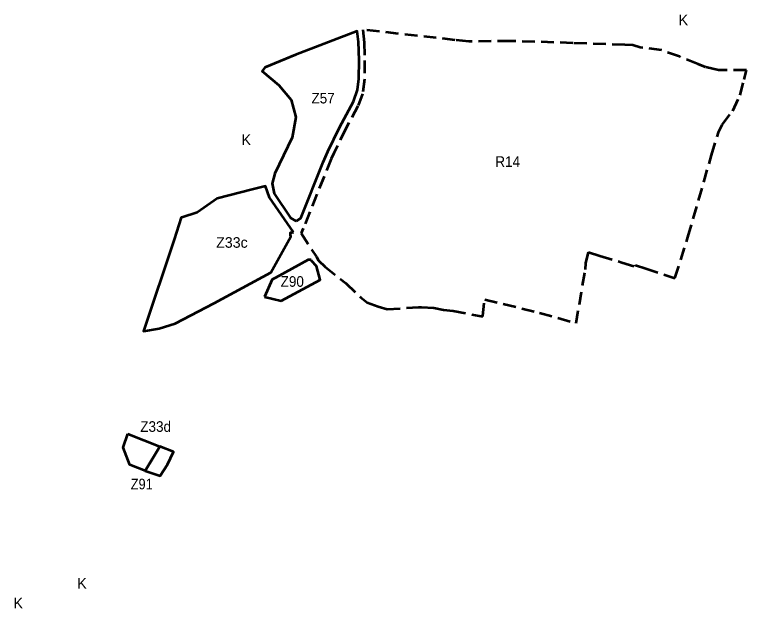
# Model space of a CAD drawing. Extents: x -650246 to -642674, y -1074280 to -1066767.
# Drawn here: x -648810 to -647155, y -1074280 to -1072937 of the extents above; entities that cross this region are included whole.
import ezdxf

# ---------------------------------------------------------------- set-up
doc = ezdxf.new("R2010")
doc.units = 0
doc.header["$LTSCALE"] = 9.6
doc.linetypes.add('MEDIUM_DASHED', pattern=[4.5, 3, -1.5])
for name, color, linetype, lineweight in [('44', 7, 'Continuous', 53), ('45', 7, 'Continuous', 53), ('46', 7, 'Continuous', 13), ('48', 7, 'Continuous', 13), ('61', 7, 'MEDIUM_DASHED', 53), ('62', 7, 'Continuous', 35)]:
    doc.layers.add(name, color=color, linetype=linetype, lineweight=lineweight)

msp = doc.modelspace()

# ---------------------------------------------------------------- linework, layer by layer
at = {"layer": '44'}
msp.add_line((-648245.341, -1073575.152), (-648207, -1073584), dxfattribs=at)
for points in [[(-648139.56, -1073491.4), (-648146.4, -1073491.55), (-648220.42, -1073532.43), (-648227.63, -1073535.89), (-648245.341, -1073575.152)], [(-648207, -1073584), (-648119, -1073537), (-648127.31, -1073505.75), (-648138.41, -1073493.62), (-648139.56, -1073491.4)]]:
    msp.add_lwpolyline(points, dxfattribs=at)
msp.add_lwpolyline([(-648515.333, -1073968.584), (-648480.86, -1073980.25), (-648464.44, -1073954.69), (-648451.05, -1073925.87), (-648481.749, -1073913.76), (-648498, -1073940)], close=True, dxfattribs=at)
at = {"layer": '45'}
for points in [[(-648030.86, -1073039.71), (-648032.09, -1072998.65), (-648035.592, -1072974.222), (-648175.061, -1073027.551), (-648244.214, -1073056.657), (-648250.491, -1073064.698), (-648212.22, -1073096.39), (-648184.37, -1073129.89)], [(-648030.86, -1073039.71), (-648032.09, -1072998.65), (-648035.592, -1072974.222), (-648175.061, -1073027.551), (-648244.214, -1073056.657), (-648250.491, -1073064.698), (-648212.22, -1073096.39), (-648184.37, -1073129.89)], [(-648101.67, -1073246.63), (-648075.34, -1073191.93), (-648043.29, -1073132.97), (-648034.43, -1073107.07), (-648031.8, -1073082.07), (-648030.86, -1073039.71)], [(-648101.67, -1073246.63), (-648075.34, -1073191.93), (-648043.29, -1073132.97), (-648034.43, -1073107.07), (-648031.8, -1073082.07), (-648030.86, -1073039.71)], [(-648184.37, -1073129.89), (-648174.03, -1073168.94), (-648182.12, -1073214.56), (-648221.39, -1073296.24), (-648227.75, -1073318.75), (-648223.03, -1073341.59), (-648186.47, -1073396.47), (-648173.38, -1073404.03)], [(-648184.37, -1073129.89), (-648174.03, -1073168.94), (-648182.12, -1073214.56), (-648221.39, -1073296.24), (-648227.75, -1073318.75), (-648223.03, -1073341.59), (-648186.47, -1073396.47), (-648173.38, -1073404.03)], [(-648173.38, -1073404.03), (-648162.55, -1073397.4), (-648112.36, -1073270.87), (-648101.67, -1073246.63)], [(-648173.38, -1073404.03), (-648162.55, -1073397.4), (-648112.36, -1073270.87), (-648101.67, -1073246.63)], [(-648179.07, -1073428.81), (-648233.36, -1073350.68), (-648243.08, -1073325.04), (-648272.642, -1073332.558)], [(-648179.07, -1073428.81), (-648233.36, -1073350.68), (-648243.08, -1073325.04), (-648272.642, -1073332.558)], [(-648272.642, -1073332.558), (-648352.312, -1073353), (-648397.062, -1073384.375)], [(-648272.642, -1073332.558), (-648352.312, -1073353), (-648397.062, -1073384.375)], [(-648397.062, -1073384.375), (-648432.187, -1073395.625), (-648433.206, -1073395.51), (-648449.599, -1073445.278)], [(-648397.062, -1073384.375), (-648432.187, -1073395.625), (-648433.206, -1073395.51), (-648449.599, -1073445.278)], [(-648447.06, -1073635.39), (-648358.69, -1073589.35), (-648230.81, -1073520.18), (-648185.34, -1073438.91), (-648185.82, -1073435.12), (-648186.46, -1073430.01), (-648183.46, -1073429.52), (-648179.07, -1073428.81)], [(-648447.06, -1073635.39), (-648358.69, -1073589.35), (-648230.81, -1073520.18), (-648185.34, -1073438.91), (-648185.82, -1073435.12), (-648186.46, -1073430.01), (-648183.46, -1073429.52), (-648179.07, -1073428.81)], [(-648449.599, -1073445.278), (-648518.867, -1073652.836), (-648483.58, -1073646.7), (-648447.06, -1073635.39), (-648447.06, -1073635.39)], [(-648449.599, -1073445.278), (-648518.867, -1073652.836), (-648483.58, -1073646.7), (-648447.06, -1073635.39), (-648447.06, -1073635.39)]]:
    msp.add_lwpolyline(points, dxfattribs=at)
msp.add_lwpolyline([(-648554.42, -1073885.092), (-648481.749, -1073913.76), (-648515.333, -1073968.584), (-648549.76, -1073954.86), (-648564.75, -1073915.91)], close=True, dxfattribs=at)
at = {"layer": '61'}
msp.add_lwpolyline([(-648019.38, -1072999.62), (-648018.59, -1073040.65), (-648019.04, -1073082.7), (-648023.38, -1073115.63), (-648033.71, -1073143.76), (-648060.75, -1073194.72), (-648088.41, -1073249.9), (-648094.092, -1073263.034), (-648157.74, -1073420.89), (-648161.7, -1073431.46), (-648127.64, -1073484.76), (-648122.58, -1073492.69), (-648107.53, -1073507.68), (-648060.92, -1073544.52), (-648027.7, -1073575.75), (-648012.55, -1073588.03), (-647987.9, -1073597.16), (-647967.15, -1073602.95), (-647896.59, -1073598.78), (-647889.64, -1073598.65), (-647861.92, -1073599.87), (-647840.12, -1073604.27), (-647818.3, -1073607.2), (-647751.31, -1073619.66), (-647751.124, -1073618.122), (-647746.63, -1073580.97), (-647622.63, -1073611.03), (-647539.83, -1073634.79), (-647519.11, -1073513.63), (-647518.27, -1073499.08), (-647511.932, -1073474.5), (-647486.04, -1073482.326), (-647436.7, -1073497.24), (-647406.33, -1073506.42), (-647405.5, -1073503.75), (-647382.45, -1073511.28), (-647316.269, -1073532.9), (-647287.03, -1073440.3), (-647233.5, -1073254.63), (-647218, -1073203.36), (-647216.34, -1073199.89), (-647209.63, -1073185.84), (-647185.73, -1073154.33), (-647168.83, -1073118.8), (-647159.72, -1073083.31), (-647154.77, -1073062.68), (-647218.06, -1073062.37), (-647247.46, -1073055.63), (-647263.8, -1073049), (-647305.94, -1073031.89), (-647346.22, -1073017.52), (-647394.782, -1073011.002), (-647411.34, -1073005.89), (-647429.65, -1073005.19), (-647547.02, -1073001.04), (-647689.11, -1072996.49), (-647777.336, -1072997.711), (-647782.72, -1072997.397), (-647813.331, -1072994.317), (-648022.279, -1072971.102)], close=True, dxfattribs=at)

# ---------------------------------------------------------------- texts
at = {"layer": '44'}
for s, width, p in [('Z90', 0.95, (-648208.451, -1073552.422)), ('Z90', 0.95, (-648208.451, -1073552.422)), ('Z91', 0.9, (-648547.629, -1074010.653))]:
    msp.add_text(s, height=24, dxfattribs=dict(at, width=width)).set_placement(p)
at = {"layer": '46', "width": 0.95}
for s, p in [('Z57', (-648138.747, -1073137.744)), ('Z57', (-648138.747, -1073137.744)), ('Z33d', (-648525.981, -1073880.565))]:
    msp.add_text(s, height=24, dxfattribs=at).set_placement(p)
at = {"layer": '46'}
msp.add_text('Z33c', height=24, dxfattribs=at).set_placement((-648354.418, -1073464.218))
msp.add_text('Z33c', height=24, dxfattribs=at).set_placement((-648354.418, -1073464.218))
at = {"layer": '48'}
for p in [(-647307.985, -1072960.845), (-647307.985, -1072960.845), (-648296.955, -1073231.892), (-648668.641, -1074235.329), (-648812.985, -1074279.86)]:
    msp.add_text('K', height=24, dxfattribs=at).set_placement(p)
at = {"layer": '62', "width": 0.95}
msp.add_text('R14', height=24, dxfattribs=at).set_placement((-647722.71, -1073281.294))

doc.saveas('drawing.dxf')
